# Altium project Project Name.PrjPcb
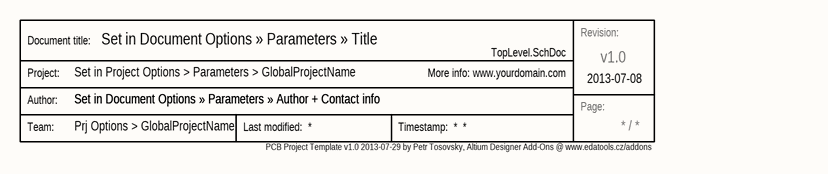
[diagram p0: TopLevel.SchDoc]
GlobalProjectLink: www.yourdomain.com; GlobalProjectName: Set in Project Options > Parameters > GlobalProjectName; GlobalProjectRevision: v1.0; GlobalProjectTeam: Prj Options > GlobalProjectName; GlobalRevisionDate: 2013-07-08
1 sheet, 1 parts. Net scope: global (net labels, ports and power ports of the same name join across sheets).
Board file: 4 Layer PCB template.PcbDoc

## Sheet TopLevel.SchDoc: Set in Document Options » Parameters » Title
size A4; Author: Set in Document Options » Parameters » Author + Contact info

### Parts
Stamp  Stamp  (value not drawn)  (graphical)

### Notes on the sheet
- PCB Project Template v1.0 2013-07-29 by Petr Tosovsky, Altium Designer Add-Ons @ www.edatools.cz/addons <http://www.edatools.cz/addons>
